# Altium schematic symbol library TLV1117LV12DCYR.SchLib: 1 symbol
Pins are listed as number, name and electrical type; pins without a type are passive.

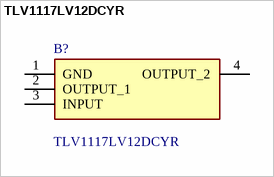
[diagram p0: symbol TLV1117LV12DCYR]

## TLV1117LV12DCYR
designator B?
1-A, Positive Fixed Voltage, Low-Dropout Regulator; Manufacturer_Name: Texas Instruments; Geometry.Height: 1.8mm
footprint SOT230P700X180-4N
pins: 1 GND, 2 OUTPUT_1, 3 INPUT, 4 OUTPUT_2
